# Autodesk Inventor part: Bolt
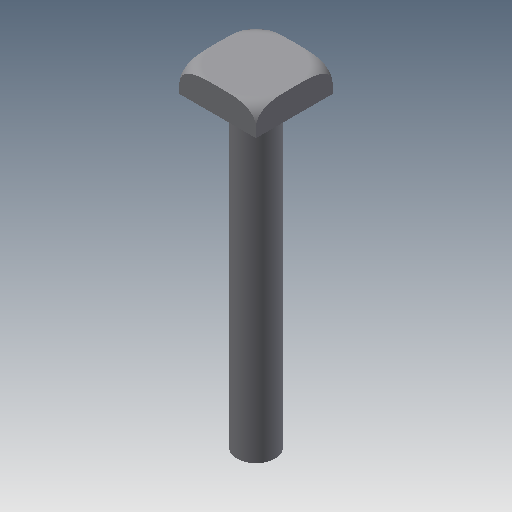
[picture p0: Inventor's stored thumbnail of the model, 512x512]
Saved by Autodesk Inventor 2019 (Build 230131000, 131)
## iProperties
Created: 2009-04
Part Number: Bolt
Document SubType Name: Modeling
Designer: Sham
Density: 1 g/cm^3
Material: Generic
Appearance: Default
Mass: 15.4123 g
Surface Area: 54.8695 cm^2
Volume: 15.4123 cm^3
Author: Sham
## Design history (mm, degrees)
sketch "Sketch1"
  geometry: L1 (-12, 12)-(12, 12); L2 (12, 12)-(12, -12); L3 (12, -12)-(-12, -12); L4 (-12, -12)-(-12, 12); 1 further point
  constraints: 8 end point, 2 parallel, 2 perpendicular, 1 horizontal, 1 other
  dimensions: "d0" = 24 distance of L1.start L1.end; "d1" = 12 distance from line of L2 point (0, 0); "d2" = 12 distance from line of L1 point (0, 0)
extrude "Extrusion1" new body sketch "Sketch1" distance "d3" = 8; taper "d4" = 0 deg
sketch "Sketch2"
  geometry: C1 r 6 at (0, 0)
  constraints: 1 centre point
  dimensions: "d5" = 12 diameter of C1
extrude "Extrusion2" join sketch "Sketch2" distance "d6" = 96; taper "d7" = 0 deg
workpoint "Work Point1"
workplane "Work Plane1"
sketch "Sketch3"
  geometry: L1 (33.941, 5)-(33.941, 6); L2 (28.941, 0)-(28.405, 0); L3 (16.971, 125.007)-(16.971, -22.043) reference; A1 r 5 centre (28.941, 5) between (28.941, 0) and (33.941, 5); 1 further point
  constraints: 4 end point, 2 point on circle, 2 point on line, 2 tangent, 1 centre point, 1 perpendicular
  dimensions: "d10" = 5 radius of A1
revolve "Revolution1" sketch "Sketch3" stored, may be unused: angle "d12" = 90 deg
body "Solid1"
other parameters: "d11" = 90 deg
